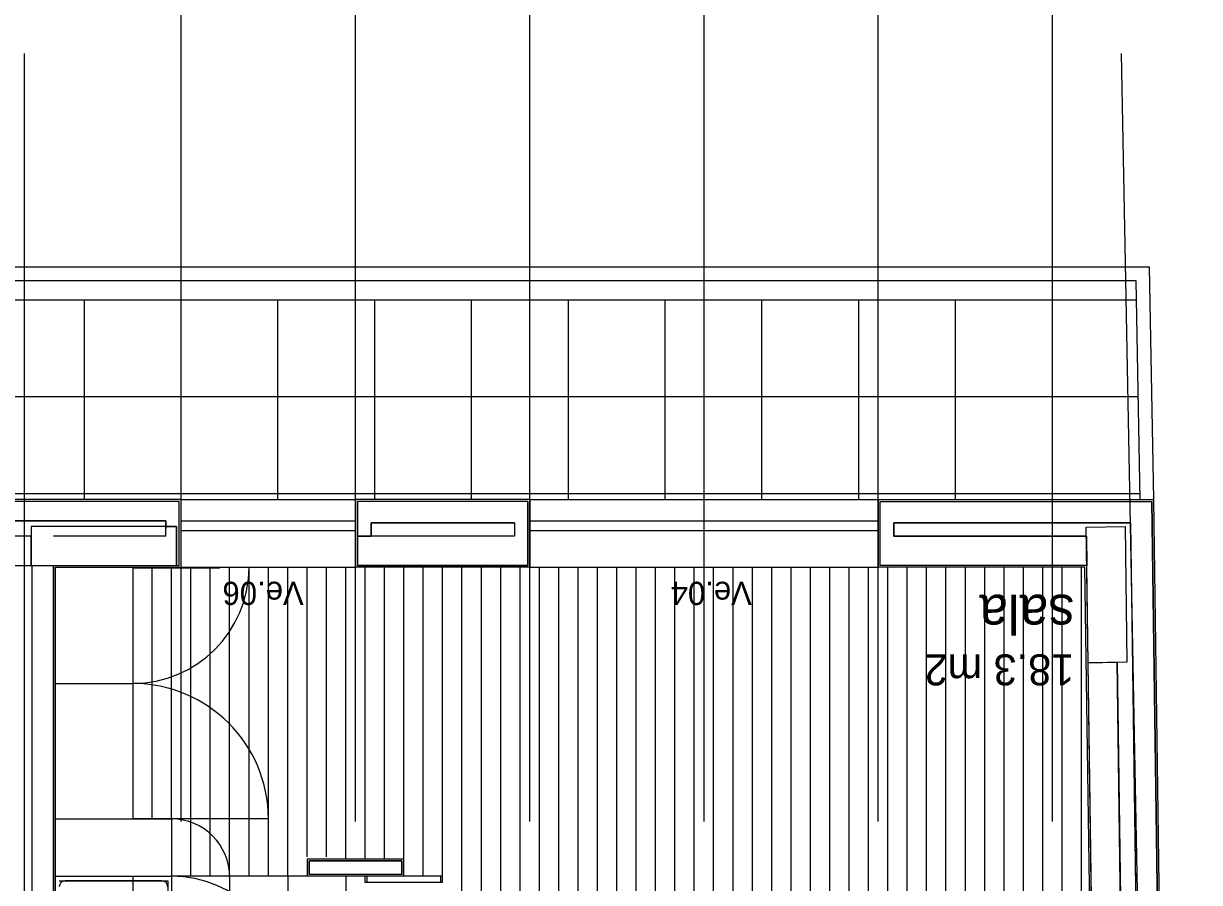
# Model space of a CAD drawing. Extents: x 1248 to 1356, y -443 to -224.
# Drawn here: x 1345.48 to 1351.55, y -233.9 to -229.47 of the extents above; entities that cross this region are included whole.
import ezdxf

# ---------------------------------------------------------------- set-up
doc = ezdxf.new("R2010")
doc.units = 0
for name, color, linetype in [('corte', 7, 'Continuous'), ('estereoctomias', 7, 'Continuous'), ('estrutura-eixos', 7, 'Continuous'), ('Level 1', 7, 'Continuous'), ('Level 10', 7, 'Continuous'), ('Level 11', 7, 'Continuous'), ('Level 13', 7, 'Continuous'), ('Level 2', 7, 'Continuous'), ('Level 3', 7, 'Continuous'), ('Level 4', 7, 'Continuous'), ('Level 40', 7, 'Continuous'), ('Level 60', 7, 'Continuous'), ('revestimentos', 7, 'Continuous'), ('vermelhos-cont', 7, 'Continuous'), ('vermelhos-tracej', 7, 'Continuous')]:
    doc.layers.add(name, color=color, linetype=linetype)

msp = doc.modelspace()

# ---------------------------------------------------------------- linework, layer by layer
at = {"layer": 'corte'}
for p, q in [((1346.2137, -232.034), (1344.574, -232.034)), ((1345.519, -232.114), (1344.574, -232.114)), ((1346.2137, -232.114), (1345.634, -232.114))]:
    msp.add_line(p, q, dxfattribs=at)
for points in [[(1346.269, -232.0639), (1345.519, -232.0639), (1345.519, -232.264), (1346.269, -232.264)], [(1351.1684, -232.0641), (1351.1785, -232.764), (1350.9782, -232.7669), (1350.9682, -232.0669)]]:
    msp.add_lwpolyline(points, close=True, dxfattribs=at)
at = {"layer": 'estereoctomias'}
for points in [[(1346.2837, -232.264), (1346.2837, -231.934), (1344.504, -231.934), (1344.504, -232.264), (1345.519, -232.264), (1345.519, -232.114), (1344.574, -232.114), (1344.574, -232.034), (1346.2137, -232.034), (1346.2137, -232.074), (1346.2137, -232.0639), (1346.269, -232.0639), (1346.269, -232.264)], [(1348.0845, -232.264), (1348.0845, -231.934), (1347.2045, -231.934), (1347.2045, -232.114), (1347.2745, -232.114), (1347.2745, -232.044), (1348.0145, -232.044), (1348.0145, -232.114), (1347.2045, -232.114), (1347.2045, -232.264)], [(1351.3669, -236.264), (1351.227, -236.264), (1351.226, -236.194), (1351.2559, -236.194), (1351.198, -232.044), (1349.9745, -232.044), (1349.9745, -232.114), (1350.9689, -232.114), (1350.9711, -232.264), (1349.9045, -232.264), (1349.9045, -231.934), (1351.3065, -231.934), (1351.3669, -236.264)], [(1345.5237, -232.264), (1345.6337, -232.264), (1345.634, -235.8713), (1345.5237, -235.8713)], [(1351.1281, -232.7648), (1351.1671, -235.562), (1351.0171, -235.5641), (1350.9782, -232.7669)], [(1347.4337, -233.7901), (1347.4337, -233.8601), (1346.9537, -233.8601), (1346.9537, -233.7901)]]:
    msp.add_lwpolyline(points, close=True, dxfattribs=at)
at = {"layer": 'estrutura-eixos'}
for p, q in [((1351.3164, -231.924), (1351.2941, -230.724)), ((1351.2464, -231.9253), (1351.2254, -230.794))]:
    msp.add_line(p, q, dxfattribs=at)
at = {"layer": 'Level 1'}
for p, q in [((1346.2837, -231.934), (1344.504, -231.934)), ((1346.2837, -232.264), (1346.2837, -231.934)), ((1348.0845, -231.934), (1347.2045, -231.934)), ((1347.2045, -231.934), (1347.2045, -232.264)), ((1348.0845, -231.934), (1348.0845, -232.264)), ((1349.9045, -231.934), (1351.3065, -231.934)), ((1349.9045, -232.264), (1349.9045, -231.934)), ((1351.3669, -236.264), (1351.3065, -231.934)), ((1346.2137, -232.114), (1346.2137, -232.034)), ((1348.0145, -232.044), (1347.2745, -232.044)), ((1347.2745, -232.044), (1347.2745, -232.114)), ((1348.0145, -232.044), (1348.0145, -232.114)), ((1349.9745, -232.044), (1351.198, -232.044)), ((1349.9745, -232.114), (1349.9745, -232.044)), ((1351.2559, -236.194), (1351.198, -232.044)), ((1348.0145, -232.114), (1347.2745, -232.114)), ((1350.9689, -232.114), (1349.9745, -232.114)), ((1344.504, -232.264), (1345.6337, -232.264)), ((1345.5237, -235.8713), (1345.5237, -232.264)), ((1345.6337, -236.364), (1345.6337, -232.264)), ((1345.634, -232.264), (1346.2837, -232.264)), ((1348.0845, -232.264), (1347.2045, -232.264)), ((1350.971, -232.264), (1349.9045, -232.264)), ((1351.0269, -236.264), (1350.9711, -232.264)), ((1351.1769, -236.2619), (1351.1281, -232.7648)), ((1346.9537, -233.7901), (1346.9537, -233.8601)), ((1347.4337, -233.7901), (1346.9537, -233.7901)), ((1347.4337, -233.8601), (1347.4337, -233.7901)), ((1347.4337, -233.8601), (1346.9537, -233.8601)), ((1347.2437, -233.9021), (1347.2437, -233.8701)), ((1347.6437, -233.9021), (1347.2437, -233.9021)), ((1347.2537, -233.9021), (1347.2537, -233.8701)), ((1347.6437, -233.8701), (1347.4437, -233.8701)), ((1347.6337, -233.9021), (1347.6337, -233.8701)), ((1347.6437, -233.9021), (1347.6437, -233.8701))]:
    msp.add_line(p, q, dxfattribs=at)
at = {"layer": 'Level 10'}
for p, q in [((1345.4933, -230.894), (1340.0933, -230.894)), ((1351.2272, -230.894), (1345.4933, -230.894)), ((1345.7933, -231.924), (1345.7933, -230.894)), ((1346.2933, -231.924), (1346.2933, -230.894)), ((1346.7933, -231.924), (1346.7933, -230.894)), ((1347.2933, -231.924), (1347.2933, -230.894)), ((1347.7933, -231.924), (1347.7933, -230.894)), ((1348.2933, -231.924), (1348.2933, -230.894)), ((1348.7933, -231.924), (1348.7933, -230.894)), ((1349.2933, -231.924), (1349.2933, -230.894)), ((1349.7933, -231.924), (1349.7933, -230.894)), ((1350.2933, -231.924), (1350.2933, -230.894)), ((1350.7933, -231.924), (1350.7933, -230.894)), ((1345.4933, -231.394), (1340.0933, -231.394)), ((1351.2365, -231.394), (1345.4933, -231.394)), ((1345.4933, -231.894), (1340.0933, -231.894)), ((1351.2458, -231.894), (1345.4933, -231.894)), ((1346.1437, -233.574), (1346.1437, -232.274)), ((1346.2437, -233.574), (1346.2437, -232.274)), ((1346.3437, -233.8701), (1346.3437, -232.274)), ((1346.4437, -233.8701), (1346.4437, -232.274)), ((1346.5437, -233.8701), (1346.5437, -232.274)), ((1346.6437, -233.8701), (1346.6437, -232.274)), ((1346.7437, -233.8701), (1346.7437, -232.274)), ((1346.8437, -233.8701), (1346.8437, -232.274)), ((1346.9437, -233.7701), (1346.9437, -232.274)), ((1347.0437, -233.7701), (1347.0437, -232.274)), ((1347.1437, -233.7801), (1347.1437, -232.274)), ((1347.2437, -233.7801), (1347.2437, -232.274)), ((1347.3437, -233.7801), (1347.3437, -232.274)), ((1347.4437, -233.7801), (1347.4437, -232.274)), ((1347.5437, -233.8701), (1347.5437, -232.274)), ((1347.6437, -233.8701), (1347.6437, -232.274)), ((1347.7437, -237.859), (1347.7437, -232.274)), ((1347.8437, -237.859), (1347.8437, -232.274)), ((1347.9437, -237.874), (1347.9437, -232.274)), ((1348.0437, -237.874), (1348.0437, -232.274)), ((1348.1437, -237.874), (1348.1437, -232.274)), ((1348.2437, -237.874), (1348.2437, -232.274)), ((1348.3437, -236.074), (1348.3437, -232.274)), ((1348.4437, -236.074), (1348.4437, -232.274)), ((1348.5437, -236.074), (1348.5437, -232.274)), ((1348.6437, -236.074), (1348.6437, -232.274)), ((1348.7437, -236.074), (1348.7437, -232.274)), ((1348.8437, -236.074), (1348.8437, -232.274)), ((1348.9437, -236.074), (1348.9437, -232.274)), ((1349.0437, -236.074), (1349.0437, -232.274)), ((1349.1437, -236.074), (1349.1437, -232.274)), ((1349.2437, -236.074), (1349.2437, -232.274)), ((1349.3437, -236.074), (1349.3437, -232.274)), ((1349.4437, -236.074), (1349.4437, -232.274)), ((1349.5437, -236.074), (1349.5437, -232.274)), ((1349.6437, -236.074), (1349.6437, -232.274)), ((1349.7437, -236.074), (1349.7437, -232.274)), ((1349.8437, -236.074), (1349.8437, -232.274)), ((1349.9437, -236.074), (1349.9437, -232.274)), ((1350.0437, -236.074), (1350.0437, -232.274)), ((1350.1437, -236.074), (1350.1437, -232.274)), ((1350.2437, -236.074), (1350.2437, -232.274)), ((1350.3437, -236.074), (1350.3437, -232.274)), ((1350.4437, -236.074), (1350.4437, -232.274)), ((1350.5437, -236.074), (1350.5437, -232.274)), ((1350.6437, -236.074), (1350.6437, -232.274)), ((1350.7437, -236.074), (1350.7437, -232.274)), ((1350.8437, -236.074), (1350.8437, -232.274)), ((1350.9437, -236.074), (1350.9437, -232.274)), ((1346.9437, -233.8701), (1346.2437, -233.8701)), ((1346.5437, -233.8701), (1346.5437, -236.274)), ((1346.8437, -233.8701), (1346.8437, -236.274)), ((1347.1437, -233.8701), (1347.1437, -236.274))]:
    msp.add_line(p, q, dxfattribs=at)
at = {"layer": 'Level 11'}
msp.add_line((1346.1938, -233.894), (1345.6938, -233.894), dxfattribs=at)
for centre, start, end in [((1345.6938, -233.9239), 90.00001, 179.99979), ((1346.1938, -233.9239), 359.99998, 89.99995)]:
    msp.add_arc(centre, 0.03, start, end, dxfattribs=at)
at = {"layer": 'Level 13'}
for p, q in [((1346.0437, -232.274), (1346.0437, -233.574)), ((1345.6437, -233.574), (1346.2437, -233.574)), ((1346.2437, -233.574), (1346.2437, -236.274))]:
    msp.add_line(p, q, dxfattribs=at)
at = {"layer": 'Level 2'}
for p, q in [((1345.4933, -230.724), (1340.0933, -230.724)), ((1351.2941, -230.724), (1345.4933, -230.724)), ((1345.4933, -230.794), (1340.0933, -230.794)), ((1351.2254, -230.794), (1345.4933, -230.794)), ((1346.2937, -231.924), (1347.1945, -231.924)), ((1348.0945, -231.924), (1349.8945, -231.924)), ((1346.2937, -232.034), (1347.1945, -232.034)), ((1346.2937, -232.084), (1347.1945, -232.084)), ((1348.0945, -232.034), (1349.8945, -232.034)), ((1348.0945, -232.084), (1349.8945, -232.084)), ((1346.2937, -232.274), (1347.1945, -232.274)), ((1348.0945, -232.274), (1349.8945, -232.274))]:
    msp.add_line(p, q, dxfattribs=at)
at = {"layer": 'Level 3'}
for p, q in [((1345.6437, -232.874), (1346.0437, -232.874)), ((1346.0437, -233.8701), (1346.2437, -233.8701)), ((1346.0437, -233.874), (1346.0437, -235.074))]:
    msp.add_line(p, q, dxfattribs=at)
at = {"layer": 'Level 4'}
for p, q in [((1346.0437, -232.276), (1346.4937, -232.276)), ((1346.7437, -233.574), (1346.0437, -233.574)), ((1345.6437, -233.8701), (1346.2437, -233.8701)), ((1345.6637, -233.894), (1346.2237, -233.894)), ((1346.2237, -233.894), (1346.2237, -234.454)), ((1346.5437, -233.8701), (1346.2437, -233.8701))]:
    msp.add_line(p, q, dxfattribs=at)
for centre, radius, start, end in [((1346.0437, -232.274), 0.6, 270, 0), ((1346.2437, -233.874), 0.3, 0, 90), ((1346.2437, -234.4701), 0.6, 0, 90)]:
    msp.add_arc(centre, radius, start, end, dxfattribs=at)
msp.add_ellipse((1346.0437, -233.574), major_axis=(0, 0.7), ratio=0.999989, start_param=4.712389, end_param=6.283185, dxfattribs=at)
at = {"layer": 'revestimentos'}
for p, q in [((1346.2937, -231.924), (1344.494, -231.924)), ((1346.2937, -232.274), (1346.2937, -231.924)), ((1347.1945, -231.924), (1347.1945, -232.274)), ((1348.0945, -231.924), (1347.1945, -231.924)), ((1348.0945, -231.924), (1348.0945, -232.274)), ((1349.8945, -232.274), (1349.8945, -231.924)), ((1349.8945, -231.924), (1351.3164, -231.924)), ((1351.3771, -236.274), (1351.3164, -231.924)), ((1345.6437, -236.274), (1345.6437, -232.274)), ((1345.6437, -232.274), (1346.2937, -232.274)), ((1348.0945, -232.274), (1347.1945, -232.274)), ((1350.9612, -232.274), (1349.8945, -232.274)), ((1351.017, -236.274), (1350.9612, -232.274)), ((1346.9437, -233.7801), (1347.4437, -233.7801)), ((1346.9437, -233.7801), (1346.9437, -233.8701)), ((1347.4437, -233.8701), (1347.4437, -233.7801)), ((1347.4437, -233.8701), (1346.9437, -233.8701))]:
    msp.add_line(p, q, dxfattribs=at)
at = {"layer": 'vermelhos-cont'}
for p, q in [((1345.484, -250.7923), (1345.484, -229.6198)), ((1351.1483, -229.6198), (1351.553, -250.7923))]:
    msp.add_line(p, q, dxfattribs=at)
at = {"layer": 'vermelhos-tracej'}
for p, q in [((1346.294, -233.587), (1346.294, -228.3936)), ((1347.194, -233.587), (1347.194, -228.3936)), ((1348.094, -233.587), (1348.094, -228.3936)), ((1348.994, -233.587), (1348.994, -228.3936)), ((1349.894, -233.587), (1349.894, -228.3936)), ((1350.794, -233.587), (1350.794, -228.3936))]:
    msp.add_line(p, q, dxfattribs=at)

# ---------------------------------------------------------------- texts
at = {"layer": 'Level 40'}
for s, p in [('Ve.06', (1346.9261, -232.3487)), ('Ve.04', (1349.2408, -232.3487))]:
    msp.add_text(s, height=0.12, rotation=179.99999, dxfattribs=at).set_placement(p)
at = {"layer": 'Level 60'}
for s, height, p in [('sala', 0.2, (1350.906, -232.4159)), ('18.3 m2', 0.16, (1350.906, -232.7237))]:
    msp.add_text(s, height=height, rotation=180, dxfattribs=at).set_placement(p)

doc.saveas('drawing.dxf')
